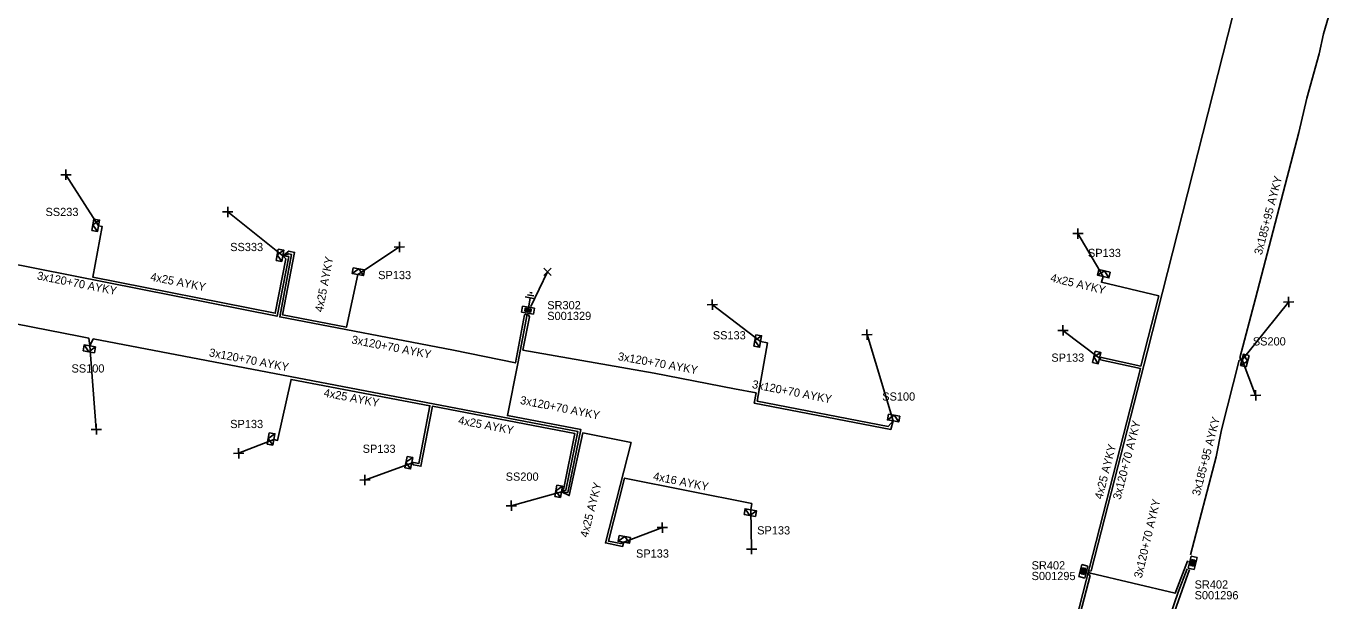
# Model space of a CAD drawing. Extents: x -762500 to -761285, y -1155006 to -1154135.
# Drawn here: x -762085.9 to -761927.2, y -1154729.3 to -1154659.6 of the extents above; entities that cross this region are included whole.
import ezdxf

# ---------------------------------------------------------------- set-up
doc = ezdxf.new("R2010")
doc.units = 0
for name, color, linetype in [('Vrstva 15', 7, 'Continuous'), ('Vrstva 28', 7, 'Continuous'), ('Vrstva 29', 7, 'Continuous'), ('Vrstva 30', 7, 'Continuous'), ('Vrstva 31', 7, 'Continuous'), ('Vrstva 33', 7, 'Continuous'), ('Vrstva 34', 7, 'Continuous'), ('Vrstva 5', 7, 'Continuous'), ('Vrstva 59', 7, 'Continuous'), ('Vrstva 6', 7, 'Continuous')]:
    doc.layers.add(name, color=color, linetype=linetype)

msp = doc.modelspace()

# ---------------------------------------------------------------- linework, layer by layer
at = {"layer": 'Vrstva 15'}
for points in [[(-762025.462, -1154692.439), (-762024.231, -1154692.656)], [(-762025.17, -1154692.176), (-762024.395, -1154692.313)], [(-762025.063, -1154693.779), (-762024.846, -1154692.548)], [(-762024.868, -1154691.909), (-762024.738, -1154691.932)], [(-762024.738, -1154691.932), (-762024.612, -1154691.955)]]:
    msp.add_lwpolyline(points, dxfattribs=at)
at = {"layer": 'Vrstva 28'}
for points in [[(-762025.781, -1154693.544), (-762025.912, -1154694.283)], [(-762025.912, -1154694.283), (-762024.435, -1154694.543)], [(-762024.304, -1154693.805), (-762025.781, -1154693.544)], [(-762025.436, -1154693.797), (-762025.502, -1154694.169)], [(-762025.502, -1154694.169), (-762024.769, -1154694.299)], [(-762025.398, -1154693.852), (-762025.447, -1154694.131)], [(-762025.447, -1154694.131), (-762024.807, -1154694.244)], [(-762024.704, -1154693.926), (-762025.436, -1154693.797)], [(-762024.758, -1154693.965), (-762025.398, -1154693.852)], [(-762025.36, -1154693.907), (-762025.393, -1154694.093)], [(-762025.393, -1154694.093), (-762024.846, -1154694.189)], [(-762024.813, -1154694.003), (-762025.36, -1154693.907)], [(-762025.321, -1154693.961), (-762025.338, -1154694.054)], [(-762025.338, -1154694.054), (-762024.884, -1154694.134)], [(-762024.868, -1154694.041), (-762025.321, -1154693.961)], [(-762024.917, -1154694.081), (-762025.289, -1154694.015)], [(-762024.884, -1154694.134), (-762024.868, -1154694.041)], [(-762024.846, -1154694.189), (-762024.813, -1154694.003)], [(-762024.807, -1154694.244), (-762024.758, -1154693.965)], [(-762024.769, -1154694.299), (-762024.704, -1154693.926)], [(-762024.435, -1154694.543), (-762024.304, -1154693.805)], [(-761957.953, -1154724.863), (-761958.316, -1154726.319)], [(-761957.226, -1154725.045), (-761957.953, -1154724.863)], [(-761957.589, -1154726.5), (-761957.226, -1154725.045)], [(-761944.724, -1154723.836), (-761945.062, -1154725.298)], [(-761944.632, -1154724.251), (-761944.8, -1154724.976)], [(-761944.8, -1154724.976), (-761944.431, -1154725.061)], [(-761944.597, -1154724.308), (-761944.743, -1154724.941)], [(-761944.743, -1154724.941), (-761944.467, -1154725.005)], [(-761943.994, -1154724.005), (-761944.724, -1154723.836)], [(-761944.562, -1154724.364), (-761944.686, -1154724.905)], [(-761944.686, -1154724.905), (-761944.502, -1154724.948)], [(-761944.264, -1154724.336), (-761944.632, -1154724.251)], [(-761944.526, -1154724.421), (-761944.63, -1154724.87)], [(-761944.63, -1154724.87), (-761944.538, -1154724.891)], [(-761944.321, -1154724.372), (-761944.597, -1154724.308)], [(-761944.574, -1154724.84), (-761944.489, -1154724.472)], [(-761944.377, -1154724.407), (-761944.562, -1154724.364)], [(-761944.538, -1154724.891), (-761944.434, -1154724.442)], [(-761944.434, -1154724.442), (-761944.526, -1154724.421)], [(-761944.502, -1154724.948), (-761944.377, -1154724.407)], [(-761944.467, -1154725.005), (-761944.321, -1154724.372)], [(-761944.431, -1154725.061), (-761944.264, -1154724.336)], [(-761944.331, -1154725.466), (-761943.994, -1154724.005)], [(-761958.316, -1154726.319), (-761957.589, -1154726.5)], [(-761957.86, -1154725.27), (-761958.04, -1154725.992)], [(-761958.04, -1154725.992), (-761957.673, -1154726.084)], [(-761957.826, -1154725.327), (-761957.983, -1154725.958)], [(-761957.983, -1154725.958), (-761957.708, -1154726.026)], [(-761957.791, -1154725.385), (-761957.926, -1154725.923)], [(-761957.926, -1154725.923), (-761957.742, -1154725.969)], [(-761957.757, -1154725.442), (-761957.868, -1154725.889)], [(-761957.868, -1154725.889), (-761957.777, -1154725.912)], [(-761957.493, -1154725.362), (-761957.86, -1154725.27)], [(-761957.551, -1154725.396), (-761957.826, -1154725.327)], [(-761957.721, -1154725.493), (-761957.812, -1154725.86)], [(-761957.608, -1154725.43), (-761957.791, -1154725.385)], [(-761957.777, -1154725.912), (-761957.665, -1154725.465)], [(-761957.665, -1154725.465), (-761957.757, -1154725.442)], [(-761957.742, -1154725.969), (-761957.608, -1154725.43)], [(-761957.708, -1154726.026), (-761957.551, -1154725.396)], [(-761957.673, -1154726.084), (-761957.493, -1154725.362)], [(-761945.062, -1154725.298), (-761944.331, -1154725.466)]]:
    msp.add_lwpolyline(points, dxfattribs=at)
at = {"layer": 'Vrstva 31'}
for points in [[(-762077.727, -1154682.997), (-762077.971, -1154684.375)], [(-762077.727, -1154682.997), (-762077.038, -1154683.118), (-762077.281, -1154684.497), (-762077.971, -1154684.375)], [(-762077.849, -1154683.686), (-762077.038, -1154683.118)], [(-762077.849, -1154683.686), (-762077.281, -1154684.497)], [(-762055.408, -1154686.636), (-762055.651, -1154688.015)], [(-762055.408, -1154686.636), (-762054.719, -1154686.758), (-762054.962, -1154688.136), (-762055.651, -1154688.015)], [(-762055.529, -1154687.326), (-762054.719, -1154686.758)], [(-762055.529, -1154687.326), (-762054.962, -1154688.136)], [(-762044.916, -1154689.157), (-762045.05, -1154689.844), (-762046.424, -1154689.577), (-762046.29, -1154688.89)], [(-762045.603, -1154689.023), (-762046.424, -1154689.577)], [(-762044.916, -1154689.157), (-762046.29, -1154688.89)], [(-762045.603, -1154689.023), (-762045.05, -1154689.844)], [(-761954.528, -1154689.445), (-761954.685, -1154690.127), (-761956.049, -1154689.812), (-761955.892, -1154689.13)], [(-761955.21, -1154689.288), (-761956.049, -1154689.812)], [(-761954.528, -1154689.445), (-761955.892, -1154689.13)], [(-761955.21, -1154689.288), (-761954.685, -1154690.127)], [(-761997.477, -1154697.026), (-761997.72, -1154698.405)], [(-761997.477, -1154697.026), (-761996.788, -1154697.148), (-761997.031, -1154698.526), (-761997.72, -1154698.405)], [(-761997.599, -1154697.715), (-761996.788, -1154697.148)], [(-761997.599, -1154697.715), (-761997.031, -1154698.526)], [(-762079.044, -1154698.948), (-762078.922, -1154698.258), (-762077.544, -1154698.501), (-762077.665, -1154699.191)], [(-762079.044, -1154698.948), (-762077.665, -1154699.191)], [(-762078.354, -1154699.069), (-762078.922, -1154698.258)], [(-762078.354, -1154699.069), (-762077.544, -1154698.501)], [(-761956.345, -1154699.008), (-761956.66, -1154700.372)], [(-761956.345, -1154699.008), (-761955.663, -1154699.165), (-761955.978, -1154700.529), (-761956.66, -1154700.372)], [(-761956.502, -1154699.69), (-761955.663, -1154699.165)], [(-761956.502, -1154699.69), (-761955.978, -1154700.529)], [(-761938.031, -1154700.902), (-761938.71, -1154700.732), (-761938.371, -1154699.374), (-761937.692, -1154699.543)], [(-761937.861, -1154700.222), (-761938.371, -1154699.374)], [(-761938.031, -1154700.902), (-761937.692, -1154699.543)], [(-761937.861, -1154700.222), (-761938.71, -1154700.732)], [(-761980.036, -1154706.892), (-761980.158, -1154707.582), (-761981.536, -1154707.339), (-761981.415, -1154706.649)], [(-761980.725, -1154706.771), (-761981.536, -1154707.339)], [(-761980.036, -1154706.892), (-761981.415, -1154706.649)], [(-761980.725, -1154706.771), (-761980.158, -1154707.582)], [(-762056.474, -1154708.886), (-762056.741, -1154710.261)], [(-762056.474, -1154708.886), (-762055.786, -1154709.02), (-762056.054, -1154710.394), (-762056.741, -1154710.261)], [(-762056.607, -1154709.573), (-762055.786, -1154709.02)], [(-762056.607, -1154709.573), (-762056.054, -1154710.394)], [(-762039.763, -1154711.777), (-762040.03, -1154713.151)], [(-762039.763, -1154711.777), (-762039.076, -1154711.91), (-762039.343, -1154713.285), (-762040.03, -1154713.151)], [(-762039.897, -1154712.464), (-762039.076, -1154711.91)], [(-762039.897, -1154712.464), (-762039.343, -1154713.285)], [(-762021.627, -1154715.237), (-762021.87, -1154716.615)], [(-762021.627, -1154715.237), (-762020.938, -1154715.358), (-762021.181, -1154716.737), (-762021.87, -1154716.615)], [(-762021.749, -1154715.926), (-762020.938, -1154715.358)], [(-762021.749, -1154715.926), (-762021.181, -1154716.737)], [(-761998.914, -1154718.788), (-761998.792, -1154718.099), (-761997.414, -1154718.342), (-761997.535, -1154719.031)], [(-761998.914, -1154718.788), (-761997.535, -1154719.031)], [(-761998.225, -1154718.91), (-761998.792, -1154718.099)], [(-761998.225, -1154718.91), (-761997.414, -1154718.342)], [(-762012.686, -1154721.593), (-762012.808, -1154722.282), (-762014.187, -1154722.039), (-762014.065, -1154721.35)], [(-762013.376, -1154721.471), (-762014.187, -1154722.039)], [(-762012.686, -1154721.593), (-762014.065, -1154721.35)], [(-762013.376, -1154721.471), (-762012.808, -1154722.282)]]:
    msp.add_lwpolyline(points, dxfattribs=at)
at = {"layer": 'Vrstva 34'}
for points in [[(-762081.119, -1154678.255), (-762081.141, -1154677.005)], [(-762081.755, -1154677.641), (-762080.505, -1154677.619)], [(-762062.125, -1154682.141), (-762060.875, -1154682.119)], [(-762061.489, -1154682.755), (-762061.511, -1154681.505)], [(-761959.065, -1154684.761), (-761957.815, -1154684.739)], [(-761958.429, -1154685.375), (-761958.451, -1154684.125)], [(-762041.315, -1154686.391), (-762040.065, -1154686.369)], [(-762040.679, -1154687.005), (-762040.701, -1154685.755)], [(-762023.192, -1154688.938), (-762022.308, -1154689.822)], [(-762023.192, -1154689.822), (-762022.308, -1154688.938)], [(-762003.375, -1154693.391), (-762002.125, -1154693.369)], [(-762002.739, -1154694.005), (-762002.761, -1154692.755)], [(-761933.505, -1154693.051), (-761932.255, -1154693.029)], [(-761932.869, -1154693.665), (-761932.891, -1154692.415)], [(-761983.989, -1154697.625), (-761984.011, -1154696.375)], [(-761960.875, -1154696.511), (-761959.625, -1154696.489)], [(-761960.239, -1154697.125), (-761960.261, -1154695.875)], [(-761984.625, -1154697.011), (-761983.375, -1154696.989)], [(-761937.515, -1154704.371), (-761936.265, -1154704.349)], [(-761936.879, -1154704.985), (-761936.901, -1154703.735)], [(-762078.065, -1154708.511), (-762076.815, -1154708.489)], [(-762077.429, -1154709.125), (-762077.451, -1154707.875)], [(-762060.179, -1154712.005), (-762060.201, -1154710.755)], [(-762060.815, -1154711.391), (-762059.565, -1154711.369)], [(-762044.869, -1154715.255), (-762044.891, -1154714.005)], [(-762045.505, -1154714.641), (-762044.255, -1154714.619)], [(-762027.119, -1154718.375), (-762027.141, -1154717.125)], [(-762027.755, -1154717.761), (-762026.505, -1154717.739)], [(-762009.435, -1154720.391), (-762008.185, -1154720.369)], [(-762008.799, -1154721.005), (-762008.821, -1154719.755)], [(-761998.625, -1154723.011), (-761997.375, -1154722.989)], [(-761997.989, -1154723.625), (-761998.011, -1154722.375)]]:
    msp.add_lwpolyline(points, dxfattribs=at)
at = {"layer": 'Vrstva 5'}
for points in [[(-761932.02, -1154624.3), (-761931.15, -1154624.48), (-761934.67, -1154638.79), (-761938.76, -1154641.9), (-761941.96, -1154642.51), (-761943.98, -1154651.48), (-761941.3, -1154653.52), (-761939.67, -1154658.34), (-761950, -1154699), (-761956.83, -1154725.63), (-761957.25, -1154725.68)], [(-761944.79, -1154723.69), (-761941.69, -1154711.81), (-761941.04, -1154708.54), (-761938.88, -1154700.1), (-761938.54, -1154700.05), (-761938.81, -1154699.82), (-761936.91, -1154692.61), (-761931.66, -1154672.51), (-761930.68, -1154668.36), (-761929.2, -1154662.96), (-761928.65, -1154660.56), (-761927.17, -1154655.43)], [(-762054.84, -1154687.45), (-762054.48, -1154687.8), (-762055.75, -1154694.42), (-762077.85, -1154690.05), (-762076.74, -1154683.89), (-762077.16, -1154683.81)], [(-762092.76, -1154686.66), (-762092.9, -1154687.39), (-762055.52, -1154694.77), (-762054.12, -1154687.55), (-762054.84, -1154687.45)], [(-762054.84, -1154687.45), (-762054.11, -1154686.89), (-762053.41, -1154687.04), (-762054.86, -1154694.62), (-762047.11, -1154696.11), (-762045.74, -1154689.71)], [(-762054.84, -1154687.45), (-762054.11, -1154687.2), (-762053.77, -1154687.3), (-762055.21, -1154694.86), (-762034.14, -1154698.9), (-762026.64, -1154700.43), (-762025.51, -1154694.61), (-762025.32, -1154694.51)], [(-761967.13, -1154735.43), (-761967.43, -1154734.96), (-761966.5, -1154731.5), (-761959.1, -1154733.28), (-761950.85, -1154701.1), (-761955.68, -1154700.04), (-761955.82, -1154699.85), (-761955.56, -1154699.76), (-761950.79, -1154700.82), (-761948.63, -1154692.31), (-761955.58, -1154690.66), (-761955.37, -1154689.97)], [(-762101.82, -1154698.24), (-762101.62, -1154698.07), (-762100.44, -1154693.13), (-762079.55, -1154697.2), (-762078.36, -1154697.42), (-762078.23, -1154698.37), (-762077.81, -1154697.52), (-762019.05, -1154708.75), (-762020.51, -1154715.85), (-762021.06, -1154716.05)], [(-762025.19, -1154694.54), (-762026.35, -1154700.49), (-762027.61, -1154706.81), (-762018.7, -1154708.51), (-762020.26, -1154716.12), (-762021.06, -1154716.05)], [(-762025.07, -1154694.56), (-762024.94, -1154694.83), (-762025.73, -1154698.87), (-762009.81, -1154701.69), (-762000.06, -1154703.56), (-761997.45, -1154704.06), (-761997.67, -1154705.29), (-761981.13, -1154708.49), (-761980.85, -1154707.46), (-761981.43, -1154708.12), (-761997.32, -1154705.05), (-761996.07, -1154698), (-761996.91, -1154697.84)], [(-762021.06, -1154716.05), (-762020.77, -1154715.62), (-762019.41, -1154708.99), (-762036.7, -1154705.69), (-762038.09, -1154712.96), (-762038.99, -1154712.8), (-762039.21, -1154712.6), (-762038.95, -1154712.5), (-762038.33, -1154712.61), (-762036.99, -1154705.63), (-762053.83, -1154702.44), (-762055.47, -1154709.82), (-762055.92, -1154709.71)], [(-762021.06, -1154716.05), (-762020.1, -1154716.52), (-762018.47, -1154708.91), (-762012.61, -1154710.09), (-762015.72, -1154722.25), (-762013.63, -1154722.68), (-762013.5, -1154722.16)], [(-762013.5, -1154722.16), (-762013.86, -1154722.33), (-762015.35, -1154722.02), (-762013.39, -1154714.39), (-761997.97, -1154717.47), (-761998.1, -1154718.22)], [(-761957.29, -1154725.81), (-761956.9, -1154725.9), (-761946.65, -1154728.35), (-761946.57, -1154728.12), (-761945.17, -1154724.46), (-761945.02, -1154724.54)], [(-761945.21, -1154725.4), (-761946.29, -1154728.22), (-761948.73, -1154735.39), (-761953.32, -1154752.86), (-761953.98, -1154753.7), (-761954.88, -1154757.18), (-761961.57, -1154755.63), (-761964.09, -1154754.7), (-761966.98, -1154765.99), (-761970.2, -1154778.58), (-761979.86, -1154817.19), (-761982.22, -1154826.16), (-761982.85, -1154826.44), (-761983.6, -1154824.98), (-761983.19, -1154826.55), (-761983.78, -1154826.69), (-762001.52, -1154819.9), (-762001.67, -1154819.6), (-762004.6, -1154818.43), (-762003.91, -1154816.93)], [(-761967.13, -1154735.43), (-761967.13, -1154735), (-761966.29, -1154731.86), (-761958.88, -1154733.64), (-761956.97, -1154726.2), (-761957.32, -1154725.93)], [(-761944.9, -1154725.48), (-761947.37, -1154732.42), (-761942.71, -1154737.15), (-761942.95, -1154737.4)]]:
    msp.add_lwpolyline(points, dxfattribs=at)
at = {"layer": 'Vrstva 59'}
for points in [[(-762077.16, -1154683.81), (-762081.13, -1154677.63)], [(-762054.84, -1154687.45), (-762061.5, -1154682.13)], [(-761955.37, -1154689.97), (-761958.44, -1154684.75)], [(-762045.74, -1154689.71), (-762040.69, -1154686.38)], [(-762024.77, -1154693.59), (-762022.75, -1154689.38)], [(-761996.91, -1154697.84), (-762002.75, -1154693.38)], [(-761938.54, -1154700.05), (-761932.88, -1154693.04)], [(-761955.82, -1154699.85), (-761960.25, -1154696.5)], [(-761980.85, -1154707.46), (-761984, -1154697)], [(-762078.23, -1154698.38), (-762077.44, -1154708.5)], [(-761938.54, -1154700.05), (-761936.89, -1154704.36)], [(-762055.92, -1154709.71), (-762060.19, -1154711.38)], [(-762039.21, -1154712.6), (-762044.88, -1154714.63)], [(-762021.06, -1154716.05), (-762027.13, -1154717.75)], [(-761998.1, -1154718.22), (-761998, -1154723)], [(-762013.5, -1154722.16), (-762008.81, -1154720.38)]]:
    msp.add_lwpolyline(points, dxfattribs=at)

# ---------------------------------------------------------------- texts
at = {"layer": 'Vrstva 29'}
for s, p in [('S001329', (-762022.77, -1154695.23)), ('S001295', (-761964.05, -1154726.75)), ('S001296', (-761944.29, -1154729.08))]:
    msp.add_text(s, height=0.9943, dxfattribs=at).set_placement(p)
at = {"layer": 'Vrstva 30'}
for s, p in [('SR302', (-762022.77, -1154693.93)), ('SR402', (-761964.05, -1154725.46)), ('SR402', (-761944.29, -1154727.78))]:
    msp.add_text(s, height=0.9943, dxfattribs=at).set_placement(p)
at = {"layer": 'Vrstva 33'}
for s, p in [('SS233', (-762083.6, -1154682.63)), ('SS333', (-762061.21, -1154686.88)), ('SP133', (-761957.22, -1154687.6)), ('SP133', (-762043.27, -1154690.28)), ('SS133', (-762002.7, -1154697.58)), ('SS200', (-761937.23, -1154698.32)), ('SP133', (-761961.66, -1154700.29)), ('SS100', (-762080.45, -1154701.6)), ('SS100', (-761982.16, -1154705)), ('SP133', (-762061.21, -1154708.33)), ('SP133', (-762045.15, -1154711.33)), ('SS200', (-762027.81, -1154714.71)), ('SP133', (-761997.32, -1154721.22)), ('SP133', (-762012.01, -1154724.03))]:
    msp.add_text(s, height=0.9943, dxfattribs=at).set_placement(p)
at = {"layer": 'Vrstva 6'}
for s, height, rotation, p in [('3x185+95 AYKY', 0.99429, 75.36172, (-761936.14, -1154687.41)), ('4x25 AYKY', 0.9943, 79.14271, (-762049.99, -1154694.34)), ('3x120+70 AYKY', 0.99429, 348.8272, (-762084.68, -1154690.31)), ('4x25 AYKY', 0.9943, 348.81578, (-762070.95, -1154690.43)), ('4x25 AYKY', 0.9943, 346.66067, (-761961.84, -1154690.55)), ('3x120+70 AYKY', 0.99429, 349.14423, (-762046.56, -1154698.07)), ('3x120+70 AYKY', 0.99429, 349.17825, (-762063.83, -1154699.62)), ('3x120+70 AYKY', 0.99428, 349.95547, (-762014.26, -1154700.09)), ('3x120+70 AYKY', 0.99429, 349.01844, (-761998, -1154703.47)), ('4x25 AYKY', 0.9943, 349.27294, (-762049.93, -1154704.5)), ('3x120+70 AYKY', 0.99429, 348.75279, (-762026.12, -1154705.39)), ('4x25 AYKY', 0.9943, 349.17718, (-762033.62, -1154707.82)), ('3x120+70 AYKY', 0.99429, 75.61405, (-761953.27, -1154717.07)), ('3x185+95 AYKY', 0.99429, 75.40052, (-761943.67, -1154716.61)), ('4x25 AYKY', 0.9943, 75.61903, (-761955.49, -1154717.02)), ('4x16 AYKY', 0.9943, 348.70292, (-762009.99, -1154714.61)), ('4x25 AYKY', 0.9943, 75.66825, (-762017.86, -1154721.65)), ('3x120+70 AYKY', 0.99429, 76.59566, (-761950.7, -1154726.59))]:
    msp.add_text(s, height=height, rotation=rotation, dxfattribs=at).set_placement(p)

doc.saveas('drawing.dxf')
